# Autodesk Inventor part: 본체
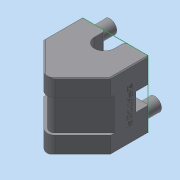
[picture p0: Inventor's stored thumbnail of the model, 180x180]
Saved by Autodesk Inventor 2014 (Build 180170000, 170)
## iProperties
Created: 2025-02
Part Number: 본체
Material: 일반
Document SubType Name: Modeling
Designer: dg
Density: 1 g/cm^3
Appearance: 기본값
Author: dg
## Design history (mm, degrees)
sketch "스케치1"
  geometry: L1 (-37, -39.5)-(37, -39.5); L2 (37, -39.5)-(37, 39.5); L3 (37, 39.5)-(-37, 39.5); L4 (-37, 39.5)-(-37, -39.5); L5 (-37, -39.5)-(37, 39.5); L6 (37, -39.5)-(-37, 39.5); L7 (-37, -2.5)-(0, -39.5); L8 (37, -2.5)-(0, -39.5); 1 further point
  constraints: 16 end point, 3 midpoint, 2 parallel, 2 perpendicular, 2 point on line, 1 horizontal
  dimensions: "d0" = 74 distance of L3.end L2.end; "d6" = 90 deg angle of L7 L8; "d7" = 42 distance from line of L8.start L3
node "작업 평면1"
extrude "돌출2" new body sketch "스케치1" distance "d8" = 74; taper "d9" = 0 deg
node "작업 평면3"
node "작업 평면4"
node "작업 평면5"
node "작업 평면7"
chamfer "모따기2" distance "d90" = 1; stored, may be unused: second distance "d91" = 2, angle "d92" = 45 deg
sketch "스케치32"
  geometry: L1 (72, 0)-(72, -74) reference; L2 (72, 0)-(0, 0) reference; L3 (-1, -1)-(-1, -73) reference; L4 (60.749, -12.251)-(36, -37); L5 (36, -37)-(72, -37); L6 (36, -37)-(11.251, -61.749); L7 (36, -37)-(1, -37); C1 r 7.5 at (11.251, -61.749); C2 r 7.5 at (60.749, -12.251); A1 r 35 centre (36, -37) between (60.749, -12.251) and (11.251, -61.749); 3 further points
  constraints: 8 end point, 3 centre point, 3 midpoint, 3 point on circle, 2 coincident, 1 collinear, 1 horizontal alignment, 1 vertical alignment
  dimensions: "d108" = 70 diameter of A1; "d110" = 45 deg angle of L5 L4; "d111" = 45 deg angle of L7 L6; "d112" = 15 diameter of C1; "d113" = 15 diameter of C2
extrude "돌출18" join sketch "스케치32" distance "d114" = 19; taper "d115" = 0 deg
sketch "스케치33"
  geometry: C1 r 7.5 at (0, 0) reference; C2 r 7.5 at (49.497, 49.497) reference; 1 further point
hole "구멍4" sketch "스케치33" at (0, 0), (49.497, 49.497) diameter "d116" = 4.917; stored, may be unused: countersink angle "d120" = 90 deg, drill point angle "d122" = 118 deg; dims "d117" = 12, "d118" = 4, "d119" = 2, "d121" = 14
fillet "모깎기7" dims "d127" = 3
node "작업 평면8"
sketch "스케치38"
  geometry: 1 further point
sketch "스케치39"
  geometry: L1 (-37, -2.5)-(-37, 38.5) reference; L2 (-36, -2.086)-(0, -38.086) reference; L3 (0, -39.5)-(-37, -2.5) reference; L4 (0, -38.086)-(36, -2.086) reference; L5 (37, 38.5)-(37, -2.5) reference; L6 (37, -2.5)-(0, -39.5) reference; L7 (-37, 1.743)-(0, -35.257); L8 (0, -35.257)-(37, 1.743); L9 (-37, 1.743)-(-37, -2.5); L10 (0, -39.5)-(-37, -2.5); L11 (0, -39.5)-(37, -2.5); L12 (37, 1.743)-(37, -2.5); 1 further point
  constraints: 12 end point, 2 collinear, 2 perpendicular, 2 point on line, 1 parallel
  dimensions: "d140" = 3 distance between parallel lines of L3 L7; "d141" = 3 distance between parallel lines of L6 L8
extrude "돌출22" cut sketch "스케치39" stored distance "d142" = 36; taper "d143" = 0 deg
fillet "모깎기8" dims "d144" = 6
fillet "모깎기9" dims "d145" = 9
sketch "스케치41"
  geometry: L1 (0, -74)-(0, 0) reference; L2 (72, -74)-(0, -74) reference; L3 (72, 0)-(72, -74) reference; L4 (72, 0)-(0, 0) reference; C1 r 10.5 at (11.251, -61.749) reference; C2 r 10.5 at (60.749, -12.251) reference; 1 further point
sketch "스케치42"
  geometry: L1 (36, 39.5)-(-36, 39.5) reference; L2 (-11, 27.5)-(-11, 39.5); L3 (11, 27.5)-(11, 39.5); A1 r 11 centre (0, 27.5) between (-11, 27.5) and (11, 27.5); 2 further points
  constraints: 4 end point, 2 perpendicular, 2 point on circle, 2 point on line, 2 tangent, 1 centre point, 1 midpoint, 1 vertical alignment
  dimensions: "d148" = 22 diameter of A1; "d149" = 12 distance from line of A1.centre L1
extrude "돌출23" cut sketch "스케치42" stored distance "d150" = 8; taper "d151" = 0 deg
sketch "스케치43"
  geometry: L1 (-73, 73)-(-73, 1) reference; C1 r 21 at (-36, 37); 2 further points
  constraints: 1 centre point, 1 horizontal alignment, 1 midpoint, 1 vertical alignment
  dimensions: "d152" = 42 diameter of C1
extrude "돌출24" cut sketch "스케치43" distance "d153" = 8; taper "d154" = 0 deg
sketch "스케치44"
  geometry: C1 r 16 at (-36, 37); A1 r 21 centre (-36, 37) between (-25, 19.111) and (-25, 54.889) reference; 1 further point
  constraints: 1 centre point, 1 coincident
  dimensions: "d155" = 32 diameter of C1
extrude "돌출25" cut sketch "스케치44" distance "d156" = 28; taper "d157" = 0 deg
sketch "스케치45"
  geometry: L1 (-72, 41)-(0, 41) reference; L2 (-3.751, 61)-(-18.751, 61) reference; 3 further points
  constraints: 1 midpoint, 1 vertical alignment, 1 other
  dimensions: "d158" = 40 distance from line of point (-36, 21) L2
feature "엠보싱3" sketch "스케치45" dims "d92" = 45 deg, "d159" = 0.5, "d160" = 0
chamfer "모따기4" distance "d161" = 1; stored, may be unused: second distance "d162" = 2, angle "d163" = 45 deg
node "작업 평면9"
sketch "스케치46"
  geometry: L1 (-37, -2.5)-(-37, 38.5) reference; L2 (36, 39.5)-(-36, 39.5) reference; L3 (-37, 25.5)-(-23, 39.5); L4 (-37, 25.5)-(-37, 38.5); L5 (-36, 39.5)-(-23, 39.5); L6 (-36, 39.5)-(-23, 39.5); L7 (-23, 39.5)-(-37, 39.5); L8 (-37, 39.5)-(-37, 38.5); 1 further point
  constraints: 12 end point, 2 collinear, 2 perpendicular, 2 point on line
  dimensions: "d164" = 14 distance from line of L3.end L1; "d165" = 14 distance from line of L3.start L2
extrude "돌출26" cut sketch "스케치46" stored distance "d166" = 20; taper "d167" = 0 deg
sketch "스케치47"
  geometry: L1 (0, 0)-(0, 20) reference; L2 (0, 0)-(19.799, 0) reference; C1 r 6.5 at (9.899, 10); 3 further points
  constraints: 2 midpoint, 1 centre point, 1 horizontal alignment, 1 vertical alignment
  dimensions: "d168" = 13 diameter of C1
extrude "돌출27" cut sketch "스케치47" distance "d169" = 3; taper "d170" = 0 deg
sketch "스케치48"
  geometry: C1 r 6.5 at (0, 0) reference; 1 further point
sketch "스케치49"
  geometry: C1 r 6.5 at (0, 0) reference; 1 further point
fillet "모깎기10" dims "d171" = 3
sketch "스케치50"
  geometry: C1 r 6.5 at (0, 0) reference; 1 further point
hole "구멍5" sketch "스케치48" diameter "d172" = 8; stored, may be unused: countersink angle "d176" = 90 deg, drill point angle "d178" = 118 deg; dims "d173" = 12, "d174" = 4, "d175" = 2, "d177" = 8
node "솔리드2"
mirror "대칭1"
mirror "대칭3"
mirror "대칭5"
mirror "대칭6"
node "작업 평면2"
node "작업 평면6"
